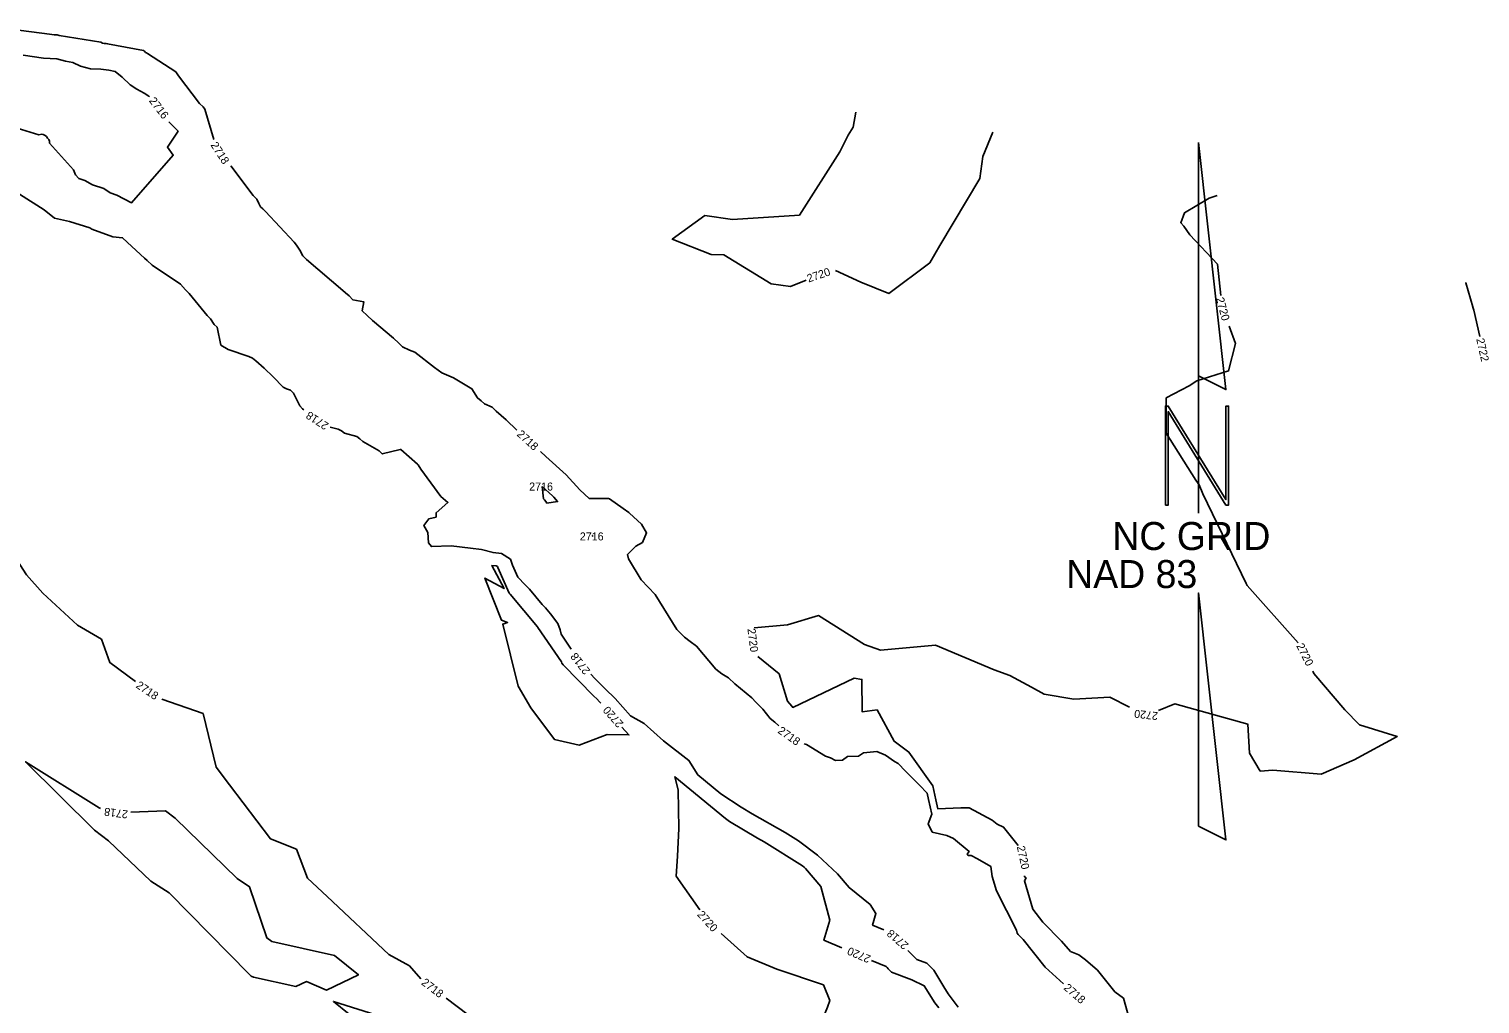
# Model space of a CAD drawing. Extents: x 1326424 to 1329294, y 1001359 to 1003823.
# Drawn here: x 1327121.9 to 1327484.6, y 1003451.1 to 1003694.7 of the extents above; entities that cross this region are included whole.
import ezdxf

# ---------------------------------------------------------------- set-up
doc = ezdxf.new("R2010")
doc.units = 0
for name, color, linetype in [('Prop Rem of Exist Asph Pvmt', 7, 'Continuous'), ('Prop Roadway Bridge', 7, 'Continuous'), ('Scratch_Level_3', 7, 'Continuous')]:
    doc.layers.add(name, color=color, linetype=linetype)

# ---------------------------------------------------------------- blocks, each defined once
blk = doc.blocks.new('CTL NORTH ARROW NAD 83')
at = {"layer": 'Prop Roadway Bridge'}
for points in [[(0.0013, 1.7432), (0.0013, 0.5773), (0.1385, 0.5085)], [(-0.1633, -0.068), (-0.1495, -0.068), (-0.1495, 0.3985), (0.1385, -0.068), (0.152, -0.068), (0.152, 0.426), (0.1385, 0.426), (0.1385, -0.0405), (-0.1495, 0.426), (-0.1633, 0.426)], [(0.0013, -1.6735), (0.1385, -1.742), (0.0013, -0.5072)]]:
    blk.add_lwpolyline(points, close=True, dxfattribs=at)
blk.add_lwpolyline([(0.0013, 0.5773), (0.0013, -0.1095)], dxfattribs=at)
for s, p in [('NC GRID', (-0.429, -0.293)), ('   NAD 83', (-0.8159, -0.483))]:
    blk.add_text(s, height=0.14, dxfattribs=at).set_placement(p)

msp = doc.modelspace()

# ---------------------------------------------------------------- linework, layer by layer
at = {"layer": 'Prop Rem of Exist Asph Pvmt'}
for points in [[(1327328.62, 1003673.93), (1327327.95, 1003670.18), (1327326.69, 1003668.16), (1327324.59, 1003664.03), (1327314.51, 1003648.22), (1327297.8, 1003647.12), (1327290.87, 1003648.14), (1327282.73, 1003642.18), (1327292.42, 1003638.39), (1327295.65, 1003638.3), (1327307.43, 1003631.01), (1327312.26, 1003630.34), (1327316.17, 1003631.94)], [(1327323.56, 1003634.39), (1327329.84, 1003631.46), (1327336.87, 1003628.64), (1327347.13, 1003636.33), (1327349.6, 1003640.63), (1327359.59, 1003657.4), (1327360.33, 1003662.83), (1327362.89, 1003668.92)], [(1327419.87, 1003628.13), (1327419.01, 1003635.99), (1327412.1, 1003643.3), (1327410.63, 1003645.42), (1327409.86, 1003646.3), (1327410.77, 1003648.81), (1327416.97, 1003652.46), (1327418.96, 1003653.11)], [(1327439.23, 1003541.34), (1327426.45, 1003555.69), (1327426.18, 1003556.18), (1327415.35, 1003578.59), (1327414.46, 1003580.83), (1327413.65, 1003581.99), (1327406.17, 1003593.7), (1327406.2, 1003602.56), (1327411.91, 1003605.52), (1327413.88, 1003606.79), (1327421.82, 1003609.27), (1327423.49, 1003616.12), (1327421.91, 1003620.45)], [(1327249.04, 1003545.29), (1327249.02, 1003545.31), (1327242.19, 1003553.47), (1327242.1, 1003553.57), (1327241.93, 1003553.74), (1327239.09, 1003560.15), (1327239.01, 1003560.38), (1327238.67, 1003560.61), (1327237.66, 1003560.7), (1327240.7, 1003554.88), (1327235.9, 1003557.52), (1327240.04, 1003546.97), (1327241.57, 1003546.4), (1327240.35, 1003546.01), (1327244.21, 1003530.49), (1327247.4, 1003525.09), (1327253.28, 1003517.19), (1327259.48, 1003515.75), (1327266.43, 1003518.41), (1327271.89, 1003518.32), (1327270.16, 1003520.28)], [(1327303.17, 1003545.05), (1327311.52, 1003545.87), (1327319.3, 1003548.14), (1327330.75, 1003540.95), (1327334.75, 1003539.48), (1327348.56, 1003540.74), (1327363.19, 1003534.59), (1327367.1, 1003533.15), (1327372.56, 1003530.28), (1327375.74, 1003528.53), (1327383.11, 1003527.28), (1327392.11, 1003527.78), (1327397.03, 1003525.23)], [(1327264.88, 1003526.28), (1327264.57, 1003526.64), (1327263.88, 1003527.32), (1327263.15, 1003528.04), (1327255.47, 1003535.81), (1327255.13, 1003536.26), (1327255.01, 1003536.56), (1327249.12, 1003545.15), (1327249.12, 1003545.17), (1327249.1, 1003545.2), (1327249.06, 1003545.25), (1327249.04, 1003545.29)], [(1327369.16, 1003490.71), (1327368.88, 1003491.15), (1327365.55, 1003495.26), (1327363.96, 1003496.05), (1327362.7, 1003497.02), (1327356.95, 1003500.12), (1327354.83, 1003500.15), (1327349.15, 1003499.85), (1327348.65, 1003502.15), (1327347.86, 1003505.59), (1327347.87, 1003505.6), (1327347.86, 1003505.65), (1327341.9, 1003514.06), (1327338.19, 1003516.74), (1327333.94, 1003524.56), (1327330.19, 1003524.14), (1327330.13, 1003532.19), (1327328.19, 1003532.49), (1327312.86, 1003525.22), (1327312.64, 1003525.48), (1327312.63, 1003525.49), (1327312.62, 1003525.5), (1327311.56, 1003526.78), (1327309.46, 1003533.56), (1327304.12, 1003537.89)], [(1327404.27, 1003524.43), (1327408.38, 1003526.06), (1327426.62, 1003521), (1327427.05, 1003513.78), (1327429.72, 1003509.31), (1327432.87, 1003509.55), (1327444.94, 1003508.51), (1327453.19, 1003512.14), (1327463.96, 1003517.95), (1327454.5, 1003520.87), (1327450.88, 1003524.58), (1327443.09, 1003533.67), (1327442.83, 1003534.24)], [(1327289.63, 1003474.62), (1327283.7, 1003483.05), (1327284.02, 1003488.05), (1327284.4, 1003494.94), (1327284.21, 1003504.62), (1327283.39, 1003507.88), (1327296, 1003497.42), (1327297.06, 1003496.73), (1327304, 1003492.57), (1327305.71, 1003491.6), (1327315.29, 1003485.6), (1327315.66, 1003485.32), (1327316.06, 1003484.95), (1327319.85, 1003480.49), (1327322.11, 1003472.04), (1327320.64, 1003467.01), (1327325.13, 1003465.11)], [(1327396.94, 1003447.44), (1327395.53, 1003452.54), (1327393.36, 1003454.15), (1327389.04, 1003459.54), (1327386.07, 1003462.13), (1327384.36, 1003463.39), (1327382.31, 1003464.2), (1327380, 1003466.83), (1327375.37, 1003471.51), (1327372.86, 1003474.82), (1327370.77, 1003481.86), (1327371.17, 1003482.62), (1327370.82, 1003482.91), (1327370.81, 1003483.12)], [(1327329.17, 1003396.16), (1327328.94, 1003396.41), (1327312, 1003414.42), (1327309.37, 1003420.45), (1327309.3, 1003423.59), (1327311.99, 1003430.64), (1327315.91, 1003433.47), (1327317.93, 1003441.53), (1327321.53, 1003450.34), (1327322.14, 1003451.99), (1327320.51, 1003455.86), (1327308.85, 1003459.83), (1327301.41, 1003462.89), (1327294.93, 1003468.69)], [(1327332.5, 1003462), (1327336.22, 1003460.44), (1327336.42, 1003460.2), (1327336.7, 1003459.88), (1327337.56, 1003459.02), (1327342.59, 1003457.17), (1327345.7, 1003455.63), (1327348.39, 1003451.38), (1327349.33, 1003450.1)]]:
    msp.add_lwpolyline(points, dxfattribs=at)
at = {"layer": 'Scratch_Level_3'}
for points in [[(1327168.15, 1003667.1), (1327165.89, 1003674.66), (1327165.47, 1003675.24), (1327164.58, 1003676.11), (1327159.27, 1003683.03), (1327158.83, 1003683.8), (1327158.59, 1003683.99), (1327151.56, 1003688.61), (1327151.31, 1003688.74), (1327151.08, 1003688.89), (1327150.81, 1003689.16), (1327150.56, 1003689.36), (1327141.58, 1003691.03), (1327141.21, 1003691.08), (1327140.72, 1003691.1), (1327140.26, 1003691.22), (1327139.9, 1003691.39), (1327129.43, 1003693.13), (1327128.93, 1003693.27), (1327128.17, 1003693.3), (1327127.02, 1003693.47), (1327117.4, 1003694.71)], [(1327152.05, 1003677.81), (1327151.91, 1003677.92), (1327150.7, 1003678.72), (1327148.89, 1003679.66), (1327147.2, 1003680.74), (1327145.24, 1003682.67), (1327143.42, 1003684.13), (1327141.87, 1003684.42), (1327139.9, 1003684.68), (1327137.28, 1003684.79), (1327134.78, 1003685.43), (1327132.86, 1003686.37), (1327131.05, 1003686.67), (1327128.84, 1003687.27), (1327125.51, 1003687.42), (1327120.45, 1003688.15)], [(1327118.95, 1003669.95), (1327124.4, 1003668.28), (1327125.09, 1003668.42), (1327125.49, 1003668.33), (1327125.92, 1003668.15), (1327126.26, 1003667.82), (1327126.52, 1003667.48), (1327126.84, 1003667.1), (1327127.05, 1003666.66), (1327127.05, 1003666.23), (1327133.02, 1003659.57), (1327133.57, 1003658.32), (1327134.38, 1003657.37), (1327135.89, 1003656.9), (1327137.81, 1003655.76), (1327140.64, 1003654.88), (1327142.23, 1003653.77), (1327143.9, 1003653.16), (1327147.56, 1003651.31), (1327157.97, 1003663.23), (1327156.53, 1003665.2), (1327159.2, 1003669.2), (1327156.85, 1003671.53)], [(1327243.84, 1003594.5), (1327241.23, 1003597.08), (1327238.72, 1003599.25), (1327237.72, 1003600.24), (1327235.76, 1003601.09), (1327234.95, 1003601.81), (1327234.06, 1003602.54), (1327232.66, 1003604.84), (1327228.07, 1003607.58), (1327225.13, 1003608.78), (1327223.31, 1003610.11), (1327218.37, 1003613.94), (1327217, 1003614.43), (1327215.29, 1003615.28), (1327214.35, 1003616.2), (1327213.05, 1003617.49), (1327207.78, 1003621.89), (1327206.46, 1003623.11), (1327205.2, 1003624.31), (1327205.59, 1003626.57), (1327202.91, 1003627.03), (1327201.93, 1003628.03), (1327201.05, 1003628.83), (1327200.4, 1003629.38), (1327191.3, 1003637.12), (1327190.36, 1003638.04), (1327189.64, 1003639.48), (1327188.81, 1003640.71), (1327188.24, 1003641.45), (1327181.05, 1003649.12), (1327180.35, 1003649.79), (1327179.82, 1003650.31), (1327179.35, 1003651.11), (1327178.84, 1003652.17), (1327177.94, 1003653.12), (1327172.4, 1003660.49)], [(1327119.57, 1003653.42), (1327125.7, 1003649.54), (1327128.3, 1003647.44), (1327132.06, 1003646.62), (1327137.09, 1003645.06), (1327137.63, 1003644.68), (1327142.87, 1003642.76), (1327145.33, 1003642.55), (1327147.61, 1003640.41), (1327150.82, 1003637.45), (1327151.44, 1003636.87), (1327152.71, 1003635.71), (1327159.76, 1003630.95), (1327161.02, 1003629.57), (1327161.92, 1003628.62), (1327166.43, 1003623.14), (1327167.3, 1003622.28), (1327168.23, 1003620.91), (1327168.94, 1003620.23), (1327169.86, 1003615.74), (1327171.71, 1003614.61), (1327176.88, 1003612.85), (1327177.83, 1003612.5), (1327178.64, 1003611.84), (1327180.69, 1003609.99), (1327182.97, 1003607.78), (1327185.42, 1003605.19), (1327186.28, 1003604.83), (1327187.25, 1003604.5), (1327188.05, 1003603.71), (1327189.59, 1003600.52), (1327190.3, 1003599.81), (1327190.64, 1003599.54)], [(1327484.58, 1003617.87), (1327483.1, 1003624.5), (1327482.88, 1003625.25), (1327482.87, 1003625.28), (1327481.14, 1003631.26), (1327481.05, 1003631.29)], [(1327148.51, 1003531.68), (1327142.11, 1003536.41), (1327140.04, 1003542.25), (1327134.06, 1003545.79), (1327125.36, 1003553.77), (1327121.28, 1003558.32), (1327108.69, 1003577.77), (1327106.3, 1003581.02), (1327106.15, 1003583.4), (1327107.35, 1003592.14), (1327114.08, 1003608.78), (1327111, 1003612.22)], [(1327197.24, 1003595.25), (1327199.18, 1003594.69), (1327200.04, 1003594.33), (1327200.77, 1003593.77), (1327203.84, 1003592.89), (1327204.63, 1003592.35), (1327205.36, 1003591.63), (1327209.44, 1003589.31), (1327210.21, 1003588.54), (1327214.73, 1003589.63), (1327214.86, 1003589.67), (1327219, 1003586.02), (1327219.23, 1003585.79), (1327219.86, 1003584.72), (1327224.91, 1003577.9), (1327226.63, 1003576.43), (1327223.67, 1003573.86), (1327223.67, 1003572.78), (1327221.83, 1003572.31), (1327220.65, 1003570.64), (1327221.58, 1003568.92), (1327221.82, 1003566.31), (1327222.53, 1003565.39), (1327227.42, 1003565.57), (1327232.31, 1003564.99), (1327235.01, 1003564.64), (1327237.94, 1003563.9), (1327240.04, 1003563.7), (1327242.27, 1003562.23), (1327242.78, 1003560.78), (1327244.11, 1003557.78), (1327245.93, 1003555.83), (1327247.01, 1003554.76), (1327250.19, 1003550.95), (1327251.05, 1003550.1), (1327252.25, 1003548.56), (1327254.12, 1003546.16), (1327254.73, 1003544.61), (1327254.92, 1003543.47), (1327257.48, 1003539.73)], [(1327309.33, 1003520.63), (1327308.34, 1003521.48), (1327307.24, 1003522.46), (1327305.35, 1003524.77), (1327304.43, 1003525.7), (1327303.62, 1003526.5), (1327302.64, 1003527.59), (1327298.34, 1003531.07), (1327296.82, 1003532.56), (1327295.15, 1003533.62), (1327293.66, 1003534.73), (1327288.78, 1003540.53), (1327287.2, 1003541.65), (1327285.8, 1003542.75), (1327283.88, 1003544.64), (1327278.47, 1003553.41), (1327274.93, 1003557.12), (1327271.76, 1003562.3), (1327271.57, 1003563.39), (1327273.6, 1003565.46), (1327275.29, 1003566.44), (1327276.31, 1003568.79), (1327275.01, 1003571), (1327272.05, 1003573.75), (1327271.87, 1003573.95), (1327270.42, 1003574.92), (1327267.03, 1003577.31), (1327266.81, 1003577.41), (1327261.96, 1003577.38), (1327259.6, 1003579.61), (1327256.22, 1003583.33), (1327251.12, 1003587.88), (1327249.76, 1003589.11)], [(1327250.2, 1003580.39), (1327252.77, 1003578.11), (1327252.84, 1003578.03), (1327253.15, 1003577.73), (1327254.05, 1003576.64), (1327251.4, 1003576.22), (1327251.13, 1003576.62), (1327250.79, 1003577.04), (1327250.51, 1003577.36), (1327250.2, 1003580.39)], [(1327262.88, 1003567.93), (1327262.8, 1003568.1), (1327262.79, 1003568.11), (1327262.78, 1003568.12), (1327262.78, 1003568.11), (1327262.79, 1003568.09), (1327262.88, 1003567.93)], [(1327262.34, 1003533.48), (1327263.35, 1003532.46), (1327265.98, 1003529.88), (1327268.46, 1003527.41), (1327272.25, 1003523.1), (1327275.71, 1003521.15), (1327280.52, 1003516.85), (1327286.91, 1003511.96), (1327289.11, 1003508.33), (1327294.83, 1003503.59), (1327299.95, 1003500.26), (1327302.68, 1003498.63), (1327310.96, 1003493.93), (1327314.28, 1003491.85), (1327319, 1003488.27), (1327324.03, 1003483.59), (1327326.93, 1003480.17), (1327332.16, 1003476), (1327333.65, 1003473.68), (1327332.82, 1003470.82), (1327335.65, 1003469.63)], [(1327219.85, 1003457.39), (1327217.07, 1003460.63), (1327211.85, 1003463.44), (1327196.48, 1003477.93), (1327191.57, 1003482.56), (1327188.78, 1003489.75), (1327182.25, 1003492.38), (1327172.05, 1003505.87), (1327168.7, 1003510.29), (1327165.45, 1003523.68), (1327155.11, 1003527.24)], [(1327380.53, 1003456.17), (1327375.92, 1003460.28), (1327370.46, 1003467.22), (1327369.21, 1003468.48), (1327368.98, 1003468.78), (1327368.76, 1003469.52), (1327363.78, 1003479.39), (1327362.7, 1003482.95), (1327362.35, 1003485.48), (1327359, 1003487.38), (1327357.46, 1003488.23), (1327356.71, 1003488.24), (1327356.47, 1003488.57), (1327356.91, 1003489.24), (1327353.02, 1003492.47), (1327351.39, 1003493.22), (1327347.74, 1003494.06), (1327346.74, 1003496.12), (1327347.59, 1003498.55), (1327346.82, 1003502.16), (1327346.44, 1003503.82), (1327344.5, 1003505.79), (1327341, 1003509.3), (1327339.17, 1003511.18), (1327338.27, 1003511.7), (1327336.06, 1003513.3), (1327333.84, 1003514.21), (1327330.54, 1003513.84), (1327329.29, 1003513.04), (1327326.54, 1003512.96), (1327325.29, 1003512), (1327323.52, 1003511.91), (1327322.31, 1003512.59), (1327321.04, 1003513.03), (1327316.32, 1003515.97), (1327315.72, 1003516.14)], [(1327177.48, 1003458.04), (1327176.98, 1003458.56), (1327156.97, 1003478.9), (1327152.36, 1003481.77), (1327141.76, 1003491.88), (1327138.33, 1003494.53), (1327121.05, 1003511.62), (1327139.46, 1003500.15), (1327139.75, 1003499.98)], [(1327147.41, 1003499), (1327156.07, 1003499.38), (1327158.47, 1003497.53), (1327173.96, 1003482.47), (1327177.04, 1003480.38), (1327181.37, 1003467.63), (1327182.62, 1003466.72), (1327198.3, 1003463.21), (1327204.25, 1003458.4), (1327196.26, 1003454.57), (1327191.29, 1003456.72), (1327188.64, 1003455.49), (1327178.07, 1003457.83), (1327177.48, 1003458.04)], [(1327341.59, 1003464.49), (1327343.89, 1003462.2), (1327346.33, 1003461.3), (1327348.14, 1003459.52), (1327350.61, 1003455.38), (1327351.69, 1003453.67), (1327354.17, 1003450.31)], [(1327224.73, 1003428.16), (1327217.63, 1003435.86), (1327198.03, 1003451.76), (1327217.88, 1003445.5), (1327233.51, 1003440.91), (1327235.38, 1003439.52), (1327237.94, 1003439.55), (1327240.84, 1003440.18), (1327240.36, 1003441.28), (1327238.94, 1003442.97), (1327237.52, 1003443.98), (1327226.21, 1003452.53)]]:
    msp.add_lwpolyline(points, dxfattribs=at)

# ---------------------------------------------------------------- block references
at = {"layer": 'Prop Roadway Bridge', "xscale": 50, "yscale": 50}
msp.add_blockref('CTL NORTH ARROW NAD 83', (1327414.19, 1003579.18), dxfattribs=at)

# ---------------------------------------------------------------- texts
at = {"layer": 'Prop Rem of Exist Asph Pvmt'}
for rotation, p in [(18.3469, (1327316.79, 1003631.37)), (284.9072, (1327418.65, 1003627.41)), (277.5351, (1327301.51, 1003544.81)), (296.9, (1327438.65, 1003540.62)), (131.3414, (1327270.64, 1003521.25)), (173.6657, (1327404.25, 1003523.99)), (282.2673, (1327368.85, 1003490.4)), (311.813, (1327288.82, 1003473.36)), (157.1325, (1327332.51, 1003463.09))]:
    msp.add_text('2720', height=2, rotation=rotation, dxfattribs=at).set_placement(p)
at = {"layer": 'Scratch_Level_3'}
for s, rotation, p in [('2716', 307.3708, (1327151.8, 1003676.76)), ('2718', 302.6842, (1327167.22, 1003665.73)), ('2722', 282.6278, (1327483.7, 1003617.25)), ('2718', 146.9832, (1327197, 1003596.07)), ('2718', 317.6774, (1327243.72, 1003593.25)), ('2718', 127.8515, (1327262.35, 1003534.4)), ('2718', 326.0662, (1327148.47, 1003530.29)), ('2718', 324.9081, (1327308.93, 1003518.97)), ('2718', 172.7345, (1327146.76, 1003499.41)), ('2718', 139.1156, (1327341.95, 1003466.02)), ('2718', 322.6182, (1327219.83, 1003456.12)), ('2718', 319.0204, (1327380.42, 1003454.9))]:
    msp.add_text(s, height=2, rotation=rotation, dxfattribs=at).set_placement(p)
for p in [(1327246.95, 1003579.39), (1327259.62, 1003566.93)]:
    msp.add_text('2716', height=2, dxfattribs=at).set_placement(p)

doc.saveas('drawing.dxf')
